(* Logix 5000 project; controller ZaxisVmpSample 1769-L16ER-BB1B rev 30.11; software revision 30.00 *)

TASK MainTask (continuous, watchdog 500 ms) : MainProgram, VMP_Interface

MODULES
   Local : 1769-L16ER-BB1B (PointIO 0, rev 30.11)
      Pump02 : ETHERNET-MODULE (Ethernet 192.168.168.122, rev 1.1, Output RPI 20 ms)
      Pump01 : ETHERNET-MODULE (Ethernet 192.168.1.131, rev 1.1, Output RPI 20 ms)
      Discrete_IO : Embedded (PointIO 1, rev 30.11, Output RPI 20 ms)
           Local:1:I.Data.0   // Green Push Btn
           Local:1:I.Data.1   // Red Push Btn
END_MODULES

TYPE VMP_Cfg :
STRUCT
   ReadyInterlock : BOOL;   // RdyInputEnabled
   CEthernetRunReady : BOOL;   // EthSendBusy
   HoldOnFault : BOOL;   // HoldOnFault
   Spare1_3 : BOOL;   // Spare Bit
   Spare1_4 : BOOL;   // Spare Bit
   Spare1_5 : BOOL;   // Spare Bit
   Spare1_6 : BOOL;   // Spare Bit
   Spare1_7 : BOOL;   // Spare Bit
   DecPlaces : SINT;   // DecimalPlaces
   SpareByte1 : SINT;   // Spare data1
   SpareByte2 : SINT;   // Spare data1
END_STRUCT
END_TYPE

TYPE VMP_IN :
STRUCT
   Ready : BOOL;   // Ready to Run
   Running : BOOL;   // Running
   Abort : BOOL;   // Abort State
   Direction : BOOL;   // Direction CCW
   ContinuousRun : BOOL;   // Continuous Run
   MotorRunning : BOOL;   // Motors Running
   AtMaxShot : BOOL;   // AtMaxShot
   CmdAck : BOOL;   // PLC Cmd Ack
   Spare1_8 : BOOL;   // Spare Bit
   Spare1_9 : BOOL;   // Spare Bit
   Spare1_10 : BOOL;   // Spare Bit
   Spare1_11 : BOOL;   // Spare Bit
   Spare1_12 : BOOL;   // Spare Bit
   Spare1_13 : BOOL;   // Spare Bit
   Spare1_14 : BOOL;   // Spare Bit
   Spare1_15 : BOOL;   // Spare Bit
   Spare1_16 : BOOL;   // Spare Bit
   Spare1_17 : BOOL;   // Spare Bit
   Spare1_18 : BOOL;   // Spare Bit
   Spare1_19 : BOOL;   // Spare Bit
   Spare1_20 : BOOL;   // Spare Bit
   Spare1_21 : BOOL;   // Spare Bit
   Spare1_22 : BOOL;   // Spare Bit
   Spare1_23 : BOOL;   // Spare Bit
   Spare1_24 : BOOL;   // Spare Bit
   Spare1_25 : BOOL;   // Spare Bit
   Spare1_26 : BOOL;   // Spare Bit
   Spare1_27 : BOOL;   // Spare Bit
   Spare1_28 : BOOL;   // Spare Bit
   FaultDispenseMotor : BOOL;   // Disp Motor Fault
   FaultAdjustMotor : BOOL;   // Adj Motor Fault
   FaultAdjustSensor : BOOL;   // Adj Sensor Fault
   CurProgram : DINT;   // Program
   CurRevolutions : DINT;   // Revolutions
   CurVolume : REAL;   // Volume
   CurRpm : DINT;   // RPM
   VolumeDint : DINT;   // Vol as Dint
   SpareDInt2 : DINT;   // Spare data2
   FineAdj : INT;   // FineAdj
   Spare_In_Int1 : INT;   // Spare_In_Int 1
END_STRUCT
END_TYPE

TYPE VMP_OUT :
STRUCT
   OkToRun : BOOL;   // Ok to Run
   Start : BOOL;   // Start
   Abort : BOOL;   // Abort Run
   Direction : BOOL;   // Direction CCW
   ContinuousRun : BOOL;   // Run Continuously
   SetMaxShotSize : BOOL;   // Set Max Volumn
   SetShotSize : BOOL;   // Set Volume
   IgnorePLC : BOOL;   // Ignore PLC Cmds
   IncFineAdj : BOOL;   // IncFineAdj
   DecFineAdj : BOOL;   // DecFineAdj
   Spare10 : BOOL;   // Spare10
   Spare11 : BOOL;   // Spare11
   Spare12 : BOOL;   // Spare12
   Spare13 : BOOL;   // Spare13
   Spare14 : BOOL;   // Spare14
   Spare15 : BOOL;   // Spare15
   Spare16 : BOOL;   // Spare16
   Spare17 : BOOL;   // Spare17
   Spare18 : BOOL;   // Spare18
   Spare19 : BOOL;   // Spare19
   Spare20 : BOOL;   // Spare20
   Spare21 : BOOL;   // Spare21
   Spare22 : BOOL;   // Spare22
   Spare23 : BOOL;   // Spare23
   Spare24 : BOOL;   // Spare24
   Spare25 : BOOL;   // Spare25
   Spare26 : BOOL;   // Spare26
   Spare27 : BOOL;   // Spare27
   Spare28 : BOOL;   // Spare28
   Spare29 : BOOL;   // Spare29
   Spare30 : BOOL;   // Spare30
   Spare31 : BOOL;   // Spare31
   Program : DINT;   // Program
   Revolutions : DINT;   // Revolutions
   Volume : REAL;   // Volume
   Rpm : DINT;   // RPM
   Spare_Out_DInt1 : DINT;   // SpareDInt1
   Spare_Out_DInt2 : DINT;   // SpareDInt2
   FineAdjOut : INT;   // FineAdj
   Spare_Out_Int1 : INT;   // Sapre_Out_Int1
END_STRUCT
END_TYPE

TYPE VMP_Prg :
STRUCT
   CalDispenseTime : BOOL;   // CalDispenseTime
   Direction : BOOL;   // Direction CCW
   SetShotSize : BOOL;   // Set Volume
   ContinuousRun : BOOL;   // Run Continuously
   Spare1_4 : BOOL;   // Spare Bit
   Spare1_5 : BOOL;   // Spare Bit
   Spare1_6 : BOOL;   // Spare Bit
   Spare1_7 : BOOL;   // Spare Bit
   Spare1_8 : BOOL;   // Spare Bit
   Spare1_9 : BOOL;   // Spare Bit
   Spare1_10 : BOOL;   // Spare Bit
   Spare1_11 : BOOL;   // Spare Bit
   Spare1_12 : BOOL;   // Spare Bit
   Spare1_13 : BOOL;   // Spare Bit
   Spare1_14 : BOOL;   // Spare Bit
   Spare1_15 : BOOL;   // Spare Bit
   Spare1_16 : BOOL;   // Spare Bit
   Spare1_17 : BOOL;   // Spare Bit
   Spare1_18 : BOOL;   // Spare Bit
   Spare1_19 : BOOL;   // Spare Bit
   Spare1_20 : BOOL;   // Spare Bit
   Spare1_21 : BOOL;   // Spare Bit
   Spare1_22 : BOOL;   // Spare Bit
   Spare1_23 : BOOL;   // Spare Bit
   Spare1_24 : BOOL;   // Spare Bit
   Spare1_25 : BOOL;   // Spare Bit
   Spare1_26 : BOOL;   // Spare Bit
   Spare1_27 : BOOL;   // Spare Bit
   Spare1_28 : BOOL;   // Spare Bit
   Spare1_29 : BOOL;   // Spare Bit
   Spare1_30 : BOOL;   // Spare Bit
   Spare1_31 : BOOL;   // Spare Bit
   Program : DINT;   // Program
   PullBack : DINT;   // PullBack
   InitialRPM : DINT;   // InitialRPM
   RPM : DINT;   // RPM
   FinalRPM : DINT;   // FinalRPM
   FineAdjust : DINT;   // FineAdjust
   Acceleration : DINT;   // Acceleration
   Deceleration : DINT;   // Deceleration
   LoopCycles : DINT;   // LoopCycles
   LinkedProgram : DINT;   // LinkedProgram
   LinkedTimeDelay : DINT;   // LinkedTimeDelay
   MotorCurrent : DINT;   // MotorCurrent
   Revolutions : DINT;   // Revolutions
   AprxDispenseTime : DINT;   // DispenseTime
   Volume : REAL;   // Volume
   ProgramName : STRING;   // ProgramName
END_STRUCT
END_TYPE

TYPE VMP_Setup :
STRUCT
   ReadyInterlock : BOOL;   // RdyInputEnabled
   EthernetRunReady : BOOL;   // EthSendBusy
   HoldOnFault : BOOL;   // HoldOnFault
   Spare1_3 : BOOL;   // Spare Bit
   Spare1_4 : BOOL;   // Spare Bit
   Spare1_5 : BOOL;   // Spare Bit
   Spare1_6 : BOOL;   // Spare Bit
   Spare1_7 : BOOL;   // Spare Bit
   Spare1_8 : BOOL;   // Spare Bit
   Spare1_9 : BOOL;   // Spare Bit
   Spare1_10 : BOOL;   // Spare Bit
   Spare1_11 : BOOL;   // Spare Bit
   Spare1_12 : BOOL;   // Spare Bit
   Spare1_13 : BOOL;   // Spare Bit
   Spare1_14 : BOOL;   // Spare Bit
   Spare1_15 : BOOL;   // Spare Bit
   Spare1_16 : BOOL;   // Spare Bit
   Spare1_17 : BOOL;   // Spare Bit
   Spare1_18 : BOOL;   // Spare Bit
   Spare1_19 : BOOL;   // Spare Bit
   Spare1_20 : BOOL;   // Spare Bit
   Spare1_21 : BOOL;   // Spare Bit
   Spare1_22 : BOOL;   // Spare Bit
   Spare1_23 : BOOL;   // Spare Bit
   Spare1_24 : BOOL;   // Spare Bit
   Spare1_25 : BOOL;   // Spare Bit
   Spare1_26 : BOOL;   // Spare Bit
   Spare1_27 : BOOL;   // Spare Bit
   Spare1_28 : BOOL;   // Spare Bit
   Spare1_29 : BOOL;   // Spare Bit
   Spare1_30 : BOOL;   // Spare Bit
   Spare1_31 : BOOL;   // Spare Bit
   Baud : DINT;   // Baud
   PumpNumber : DINT;   // PumpNumber
   SpareDInt0 : DINT;   // SpareDInt0
   SpareDInt1 : DINT;   // SpareDInt1
   FirmwareRev : REAL;   // FirmRev
   Bore : REAL;   // Bore
   SpareReal0 : REAL;   // SpareReal0
   SpareReal1 : REAL;   // SpareReal1
   SerialNumber : STRING;   // SerialNumber
END_STRUCT
END_TYPE

TYPE VMP_TcpIP_Cfg :
STRUCT
   Status : DINT;   // Status
   Config_Capability : DINT;   // Capability
   Config_Control : DINT;   // IfCtrl
   Path_Size : INT;   // Epath
   Path : SINT[4];   // Padd
   IP_Address : DINT;   // IPAddr
   Network_Address : DINT;   // NetAddr
   Gateway_Address : DINT;   // GateWay
   Name_Server : DINT;   // DNS1
   Name_Server_2 : DINT;   // DNS2
   Domain_Name : STRING;   // Domain
   Host_Name : STRING;   // Host
   Safety_Network_Number : SINT[6];   // Ignore
   TTL : SINT;   // TTL
   Alloc_Control : SINT;   // MultCast
   Reserved : SINT;   // Reserved
   Num_Mcast : INT;   // MultCastAlloc
   Mcast_Start_Addr : DINT;   // MultCastStart
   Selected_Acd : BOOL;   // ACD
   Acd_Activity : SINT;   // ACDState
   Remote_MAC : SINT[6];   // MACRmt
   Arp_Pdu : SINT[28];   // ARP_PDU
   EthernetIP_Quick_Connect : BOOL;   // QuickCon
   Encp_Inactivity_Timeout : INT;   // InactTimeout
END_STRUCT
END_TYPE

PROGRAM MainProgram   (* main routine MainRoutine *)
VAR
   Fault : ALIAS FOR VMP_IN.FaultAdjustSensor; {access Read Only}
   VMP_IN : VMP_IN;   // VMP to PLC
        .Ready   // Ready To Run
   VMP_OUT : VMP_OUT;
   VMP_Prg_Read : BOOL;
   VMP_Prg_Write : BOOL;
   VMP_Setup_Read : BOOL;
   VMP_Setup_Write : BOOL;
END_VAR

ROUTINE MainRoutine   (* ladder *)
END_ROUTINE
END_PROGRAM

PROGRAM VMP_Interface   (* main routine PumpMainRoutine *)
VAR
   DispenseEnable : BOOL;
   DispenseRevolutions : DINT := 1;
   DispenseSetup : BOOL;
   DispenseSpeed : DINT := 200;
   DispenseVolume : REAL := 0.0111;
   DispenseVolumeDint : DINT := 1110;
   DonotRun : BOOL;
   PmpIdx : DINT := 1;
   PrimeRevolutions : DINT := 10;
   PrimeSpeed : DINT := 300;
   PumpIn : VMP_IN[3] := ([1].Ready := 1, [1].AtMaxShot := 1, [1].CurRevolutions := 10, [1].CurVolume := 0.055890005, [1].CurRpm := 300, [1].VolumeDint := 5589);
   PumpOut : VMP_OUT[3] := ([1].OkToRun := 1, [1].Revolutions := 10, [1].Volume := 0.0111, [1].Rpm := 300);
   PumpPrimeEnable : BOOL;
   TestDispense : BOOL;
   TestPrime : BOOL;
   TestRun : BOOL;
   TestTimer : TIMER := (PRE := 12000);
END_VAR

ROUTINE PumpDispense   (* ladder *)
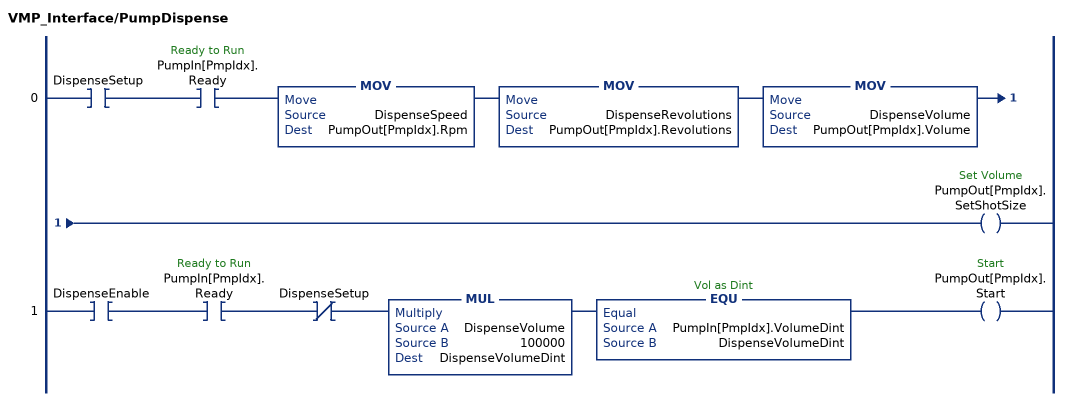
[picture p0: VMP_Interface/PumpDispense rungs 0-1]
   0: XIC(DispenseSetup)XIC(PumpIn[PmpIdx].Ready)MOV(DispenseSpeed,PumpOut[PmpIdx].Rpm)MOV(DispenseRevolutions,PumpOut[PmpIdx].Revolutions)MOV(DispenseVolume,PumpOut[PmpIdx].Volume)OTE(PumpOut[PmpIdx].SetShotSize);
   1: XIC(DispenseEnable)XIC(PumpIn[PmpIdx].Ready)XIO(DispenseSetup)MUL(DispenseVolume,100000,DispenseVolumeDint)EQU(PumpIn[PmpIdx].VolumeDint,DispenseVolumeDint)OTE(PumpOut[PmpIdx].Start);
END_ROUTINE

ROUTINE PumpMainRoutine   (* ladder *)
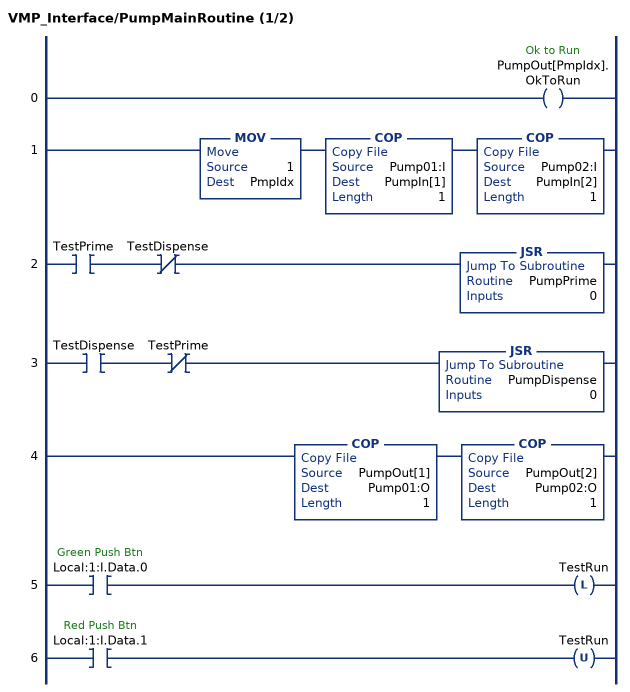
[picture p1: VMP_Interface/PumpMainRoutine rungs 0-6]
   0: OTE(PumpOut[PmpIdx].OkToRun);
   1: MOV(1,PmpIdx)COP(Pump01:I,PumpIn[1],1)COP(Pump02:I,PumpIn[2],1);
   2: XIC(TestPrime)XIO(TestDispense)JSR(PumpPrime,0);
   3: XIC(TestDispense)XIO(TestPrime)JSR(PumpDispense,0);
   4: COP(PumpOut[1],Pump01:O,1)COP(PumpOut[2],Pump02:O,1);
   5: XIC(Local:1:I.Data.0)OTL(TestRun);
   6: XIC(Local:1:I.Data.1)OTU(TestRun);
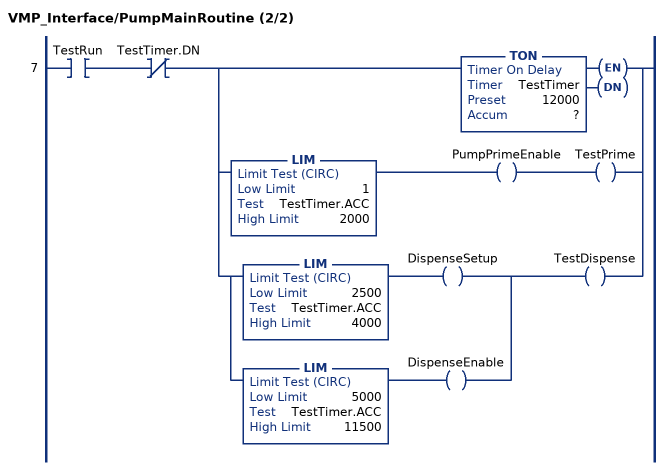
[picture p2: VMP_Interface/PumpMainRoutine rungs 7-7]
   7: XIC(TestRun)XIO(TestTimer.DN)[TON(TestTimer,?,?) ,LIM(1,TestTimer.ACC,2000) OTE(PumpPrimeEnable) OTE(TestPrime) ,[LIM(2500,TestTimer.ACC,4000) OTE(DispenseSetup) ,LIM(5000,TestTimer.ACC,11500) OTE(DispenseEnable) ] OTE(TestDispense) ];
END_ROUTINE

ROUTINE PumpPrime   (* ladder *)
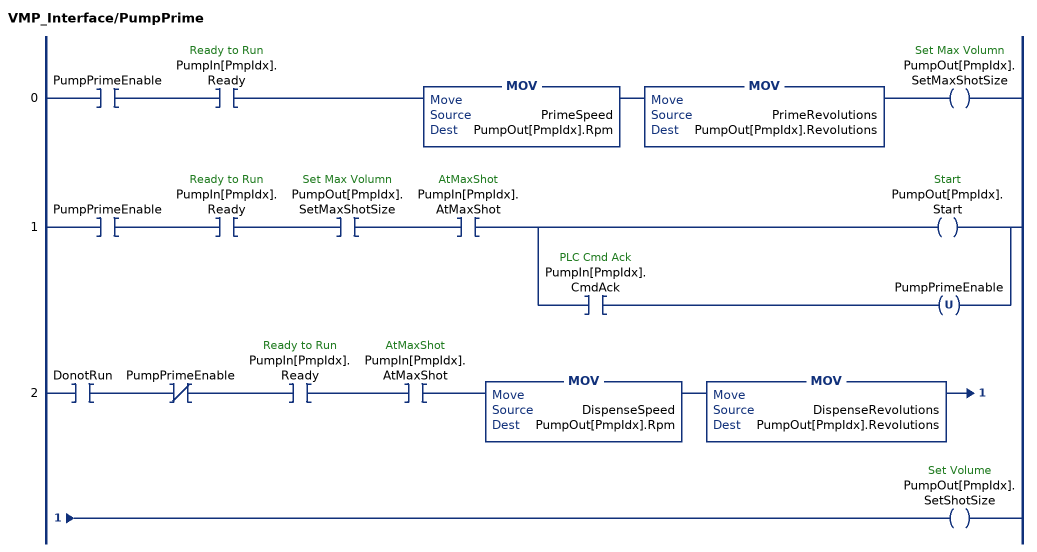
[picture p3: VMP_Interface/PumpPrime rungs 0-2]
   0: XIC(PumpPrimeEnable)XIC(PumpIn[PmpIdx].Ready)MOV(PrimeSpeed,PumpOut[PmpIdx].Rpm)MOV(PrimeRevolutions,PumpOut[PmpIdx].Revolutions)OTE(PumpOut[PmpIdx].SetMaxShotSize);
   1: XIC(PumpPrimeEnable)XIC(PumpIn[PmpIdx].Ready)XIC(PumpOut[PmpIdx].SetMaxShotSize)XIC(PumpIn[PmpIdx].AtMaxShot)[OTE(PumpOut[PmpIdx].Start) ,XIC(PumpIn[PmpIdx].CmdAck) OTU(PumpPrimeEnable) ];
   2: XIC(DonotRun)XIO(PumpPrimeEnable)XIC(PumpIn[PmpIdx].Ready)XIC(PumpIn[PmpIdx].AtMaxShot)MOV(DispenseSpeed,PumpOut[PmpIdx].Rpm)MOV(DispenseRevolutions,PumpOut[PmpIdx].Revolutions)OTE(PumpOut[PmpIdx].SetShotSize);
END_ROUTINE
END_PROGRAM
